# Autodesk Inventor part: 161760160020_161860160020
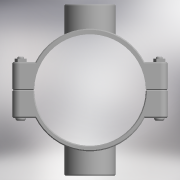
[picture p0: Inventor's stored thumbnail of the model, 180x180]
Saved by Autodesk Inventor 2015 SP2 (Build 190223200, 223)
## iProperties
Created: 2017-05
Part Number: 161760160020_161860160020
Material: Generic
Description: PLASSON DOUBLE SADDLE 160-2"
Document SubType Name: Modeling
Designer: KIM
Density: 1 g/cm^3
Appearance: Default
Author: KIM
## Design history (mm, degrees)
derived "16176.ipt"
feature "Solid1::16176.ipt"
feature "Solid2::16176.ipt"
tag "TaggingFeature1"
body "Solid1"
body "Solid2"
other parameters: "d0" = 176, "d1" = 223, "d4" = 145, "d5" = 0, "d6" = 11.15, "d7" = 223, "d8" = 0.1, "d10" = 0, "d11" = 1.6, "d20" = 1.6, "d23" = 1.6, "d36" = 15, "d37" = 12, "d38" = 88, "d39" = 0, "d40" = 3, "d41" = 5, "d42" = 0, "d44" = 3, "d45" = 0, "d46" = 1.6, "d52" = 56.656, "d54" = 0, "d57" = 0, "d58" = 172.8, "d60" = 0, "d62" = 15, "d63" = 12, "d66" = 121, "d67" = 246, "d68" = 73.6528, "d69" = 56.656, "d71" = 0, "d74" = 0, "d75" = 1.6, "G_" = 56.656, "A_" = 123, "L_" = 223, "L_1" = 145
